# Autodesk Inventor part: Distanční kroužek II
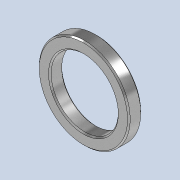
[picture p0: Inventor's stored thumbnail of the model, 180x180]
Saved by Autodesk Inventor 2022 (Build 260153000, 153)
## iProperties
Created: 2025-05
Part Number: Distanční kroužek II
Material: Všeobecné
Document SubType Name: Modeling
Designer: jbart
Density: 1 g/cm^3
Appearance: Broušená
Mass: 16.5876 g
Surface Area: 67.2116 cm^2
Volume: 16.5876 cm^3
Author: jbart
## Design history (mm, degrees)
sketch "Náčrt1"
  geometry: C1 r 25.5 at (0, 0); C2 r 34.5 at (0, 0); 1 further point
  constraints: 2 centre point, 2 coincident
  dimensions: "d0" = 51 diameter of C1; "d1" = 69 diameter of C2
extrude "Vysunutí1" new body sketch "Náčrt1" distance "d2" = 10; taper "d3" = 0 deg
chamfer "Zkosení1" distance "d4" = 1; stored, may be unused: second distance "d5" = 2, angle "d6" = 45 deg
node "Těleso1"
